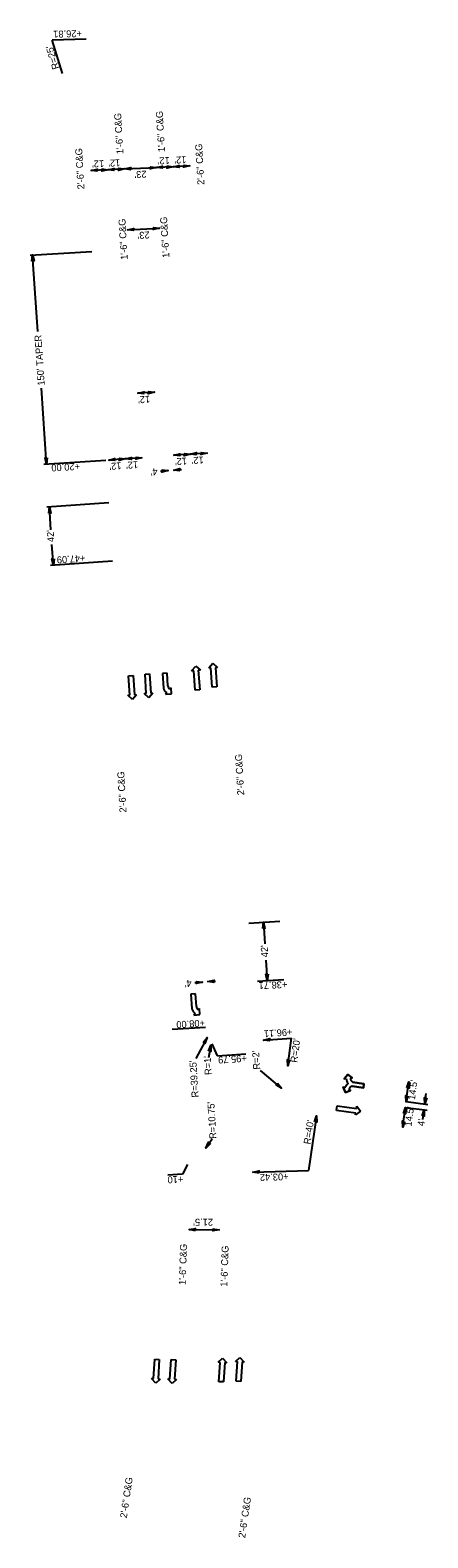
# Model space of a CAD drawing. Extents: x 2320991 to 2332664, y 598057 to 612602.
# Drawn here: x 2328311 to 2328598, y 604198 to 605283 of the extents above; entities that cross this region are included whole.
import ezdxf

# ---------------------------------------------------------------- set-up
doc = ezdxf.new("R2010")
doc.units = 0
for name, color, linetype in [('Prop Dimension', 7, 'Continuous'), ('Prop Dimension Text', 7, 'Continuous'), ('Prop Lane Arrow CELL', 7, 'Continuous'), ('Prop Terminator CELL', 7, 'Continuous')]:
    doc.layers.add(name, color=color, linetype=linetype)

msp = doc.modelspace()

# ---------------------------------------------------------------- linework, layer by layer
at = {"layer": 'Prop Dimension'}
for p, q in [((2328351.8, 605276.5), (2328327.3, 605275.8)), ((2328334.7, 605252), (2328327.3, 605275.8)), ((2328426.3, 605185.4), (2328414.3, 605184.8)), ((2328367.4, 605182.6), (2328355.4, 605182.1)), ((2328379.4, 605183.2), (2328367.4, 605182.6)), ((2328379.4, 605183.2), (2328402.3, 605184.2)), ((2328414.3, 605184.8), (2328402.3, 605184.3)), ((2328381.5, 605139.4), (2328404.5, 605140.6)), ((2328311.4, 605121.3), (2328355.9, 605123.8)), ((2328316.8, 605066.3), (2328313.1, 605121.4)), ((2328323.2, 604970.8), (2328319.5, 605025.6)), ((2328400.9, 605022.6), (2328388.9, 605021.8)), ((2328321.3, 604970.7), (2328366, 604973.7)), ((2328379.9, 604974.6), (2328368, 604973.8)), ((2328391.9, 604975.4), (2328379.9, 604974.6)), ((2328426.8, 604978), (2328414.8, 604977.2)), ((2328438.8, 604978.8), (2328426.8, 604978)), ((2328405.3, 604965.8), (2328410.8, 604966.2)), ((2328414.8, 604966.5), (2328420.3, 604966.9)), ((2328368, 604942.9), (2328323.3, 604939.9)), ((2328326.4, 604923.6), (2328325.3, 604940)), ((2328328.1, 604898.1), (2328327.1, 604913.1)), ((2328370.8, 604901), (2328326.1, 604898)), ((2328479.4, 604641.2), (2328480.5, 604625.7)), ((2328481.2, 604614), (2328482.2, 604599.3)), ((2328429.9, 604597.9), (2328435.4, 604598.2)), ((2328439.4, 604598.5), (2328444.9, 604598.9)), ((2328437.6, 604565.6), (2328413.7, 604564)), ((2328438.8, 604558.2), (2328430.6, 604543.3)), ((2328479.5, 604556.5), (2328499.5, 604557.8)), ((2328496.9, 604538), (2328499.5, 604557.8)), ((2328441.5, 604552.8), (2328439.9, 604543.6)), ((2328446.2, 604545.1), (2328442.4, 604553.7)), ((2328446.2, 604545.1), (2328466.7, 604546.5)), ((2328492.5, 604521.9), (2328477.4, 604534.5)), ((2328582.5, 604514.5), (2328584.1, 604526.4)), ((2328517.6, 604501.9), (2328511.9, 604462.7)), ((2328580.1, 604496.2), (2328581.6, 604508)), ((2328442.4, 604485.1), (2328438, 604478.7)), ((2328421.1, 604459.9), (2328410.6, 604459.3)), ((2328424.7, 604467), (2328421.1, 604459.9)), ((2328471.8, 604461.5), (2328511.9, 604462.7)), ((2328425.9, 604420.1), (2328447.4, 604419.9))]:
    msp.add_line(p, q, dxfattribs=at)
for points in [[(2328469, 604640.5), (2328491.3, 604642)], [(2328475.2, 604598.9), (2328494.1, 604600.1)]]:
    msp.add_lwpolyline(points, dxfattribs=at)
at = {"layer": 'Prop Dimension Text'}
for p, q in [((2328595.6, 604510.5), (2328596.6, 604518.1)), ((2328581.6, 604508), (2328597.3, 604506)), ((2328582.3, 604512.3), (2328597.8, 604510.2)), ((2328594.1, 604499.3), (2328595.1, 604506.3))]:
    msp.add_line(p, q, dxfattribs=at)
at = {"layer": 'Prop Lane Arrow CELL'}
for p, q in [((2328440.1, 604824.2), (2328443, 604827.6)), ((2328443, 604827.6), (2328446.4, 604824.6)), ((2328382.3, 604818.6), (2328385.6, 604818.8)), ((2328383.2, 604804.6), (2328382.3, 604818.6)), ((2328385.6, 604818.8), (2328386.5, 604804.8)), ((2328394.1, 604819.7), (2328397.4, 604820)), ((2328395, 604805.8), (2328394.1, 604819.7)), ((2328397.4, 604820), (2328398.3, 604806)), ((2328410, 604820.4), (2328406.7, 604820.2)), ((2328406.7, 604820.2), (2328407.4, 604809.7)), ((2328410.6, 604811.3), (2328410, 604820.4)), ((2328427.7, 604822.1), (2328430.6, 604825.5)), ((2328429.2, 604822.2), (2328427.7, 604822.1)), ((2328430.2, 604808.3), (2328429.2, 604822.2)), ((2328430.6, 604825.5), (2328434, 604822.6)), ((2328434, 604822.6), (2328432.5, 604822.5)), ((2328432.5, 604822.5), (2328433.5, 604808.5)), ((2328441.6, 604824.3), (2328440.1, 604824.2)), ((2328442.5, 604810.3), (2328441.6, 604824.3)), ((2328446.4, 604824.6), (2328444.9, 604824.5)), ((2328444.9, 604824.5), (2328445.8, 604810.6)), ((2328393.5, 604805.7), (2328395, 604805.8)), ((2328396.9, 604802.7), (2328393.5, 604805.7)), ((2328399.8, 604806.1), (2328396.9, 604802.7)), ((2328398.3, 604806), (2328399.8, 604806.1)), ((2328409.7, 604806.4), (2328408.8, 604805.3)), ((2328408.8, 604805.3), (2328413.1, 604805.5)), ((2328412.9, 604810), (2328411.9, 604808.9)), ((2328413.1, 604805.5), (2328412.9, 604810)), ((2328433.5, 604808.5), (2328430.2, 604808.3)), ((2328445.8, 604810.6), (2328442.5, 604810.3)), ((2328381.7, 604804.5), (2328383.2, 604804.6)), ((2328385.1, 604801.6), (2328381.7, 604804.5)), ((2328388, 604804.9), (2328385.1, 604801.6)), ((2328386.5, 604804.8), (2328388, 604804.9)), ((2328430.5, 604589.7), (2328427.2, 604589.5)), ((2328427.2, 604589.5), (2328427.9, 604578.9)), ((2328431.1, 604580.6), (2328430.5, 604589.7)), ((2328433.4, 604579.3), (2328432.4, 604578.1)), ((2328433.7, 604574.8), (2328433.4, 604579.3)), ((2328430.2, 604575.6), (2328429.3, 604574.5)), ((2328429.3, 604574.5), (2328433.7, 604574.8)), ((2328537.6, 604528.5), (2328540.1, 604531.7)), ((2328539, 604528.8), (2328537.6, 604528.5)), ((2328540.1, 604531.7), (2328543.2, 604529.3)), ((2328540.2, 604525.4), (2328540.1, 604524.9)), ((2328543.2, 604529.3), (2328541.9, 604529.1)), ((2328543.6, 604526.2), (2328551.8, 604525.1)), ((2328551.8, 604525.1), (2328551.4, 604522.1)), ((2328538.4, 604518.8), (2328536.8, 604522.5)), ((2328536.8, 604522.5), (2328538.1, 604522)), ((2328542, 604520.3), (2328538.4, 604518.8)), ((2328540.8, 604520.9), (2328542, 604520.3)), ((2328551.4, 604522.1), (2328543.2, 604523.2)), ((2328532.1, 604505.9), (2328532.5, 604509.2)), ((2328545.9, 604504), (2328532.1, 604505.9)), ((2328532.5, 604509.2), (2328546.4, 604507.3)), ((2328549.3, 604505.3), (2328545.7, 604502.6)), ((2328545.7, 604502.6), (2328545.9, 604504)), ((2328546.4, 604507.3), (2328546.6, 604508.8)), ((2328546.6, 604508.8), (2328549.3, 604505.3)), ((2328400.3, 604312.9), (2328401.1, 604326.9)), ((2328401.1, 604326.9), (2328404.4, 604326.7)), ((2328404.4, 604326.7), (2328403.6, 604312.7)), ((2328412.1, 604312.6), (2328412.9, 604326.6)), ((2328412.9, 604326.6), (2328416.2, 604326.4)), ((2328416.2, 604326.4), (2328415.4, 604312.4)), ((2328446.7, 604324.7), (2328450, 604327.7)), ((2328448.2, 604324.6), (2328446.7, 604324.7)), ((2328447.3, 604310.6), (2328448.2, 604324.6)), ((2328450, 604327.7), (2328453, 604324.3)), ((2328451.5, 604324.4), (2328450.6, 604310.5)), ((2328453, 604324.3), (2328451.5, 604324.4)), ((2328459.2, 604325.2), (2328462.5, 604328.2)), ((2328460.7, 604325.1), (2328459.2, 604325.2)), ((2328459.8, 604311.1), (2328460.7, 604325.1)), ((2328462.5, 604328.2), (2328465.5, 604324.8)), ((2328464, 604324.9), (2328463.1, 604310.9)), ((2328465.5, 604324.8), (2328464, 604324.9)), ((2328401.8, 604309.7), (2328398.8, 604313)), ((2328398.8, 604313), (2328400.3, 604312.9)), ((2328405, 604312.6), (2328401.8, 604309.7)), ((2328403.6, 604312.7), (2328405, 604312.6)), ((2328413.6, 604309.4), (2328410.6, 604312.7)), ((2328410.6, 604312.7), (2328412.1, 604312.6)), ((2328416.9, 604312.3), (2328413.6, 604309.4)), ((2328415.4, 604312.4), (2328416.9, 604312.3)), ((2328450.6, 604310.5), (2328447.3, 604310.6)), ((2328463.1, 604310.9), (2328459.8, 604311.1))]:
    msp.add_line(p, q, dxfattribs=at)
for points in [[(2328541.9, 604529.1), (2328543.2, 604529.3), (2328540.1, 604531.7), (2328537.6, 604528.5), (2328539, 604528.8)], [(2328540.2, 604525.4), (2328540.1, 604524.9)], [(2328542.6, 604527.1), (2328542.6, 604527.1)], [(2328543.2, 604523.2), (2328551.4, 604522.1), (2328551.8, 604525.1), (2328543.6, 604526.2)], [(2328538.1, 604522), (2328536.8, 604522.5), (2328538.4, 604518.8), (2328542, 604520.3), (2328540.8, 604520.9)], [(2328542, 604522.6), (2328542, 604522.6)]]:
    msp.add_lwpolyline(points, dxfattribs=at)
for centre, radius, start, end in [((2328412.5, 604810.8), 5.25, 192.6657, 237.9774), ((2328413.8, 604811.5), 3.27, 183.9897, 233.6478), ((2328433, 604580.1), 5.25, 192.6657, 237.9774), ((2328434.4, 604580.8), 3.27, 183.9897, 233.6478), ((2328544.6, 604519.6), 6.97, 129.874, 159.7268), ((2328544.6, 604519.6), 6.97, 129.874, 159.7268), ((2328545.9, 604529.4), 6.97, 185.3103, 215.0057), ((2328545.9, 604529.4), 6.97, 185.3103, 215.0057), ((2328545.9, 604529.4), 4, 184.0704, 215.0005), ((2328545.9, 604529.4), 4, 184.0704, 215.0005), ((2328544.6, 604528.3), 2.28, 211.5104, 246.2764), ((2328544.6, 604528.3), 2.28, 211.5104, 246.2764), ((2328544.6, 604519.6), 4, 129.874, 161.0867), ((2328544.6, 604519.6), 4, 129.874, 161.0867), ((2328543.6, 604521), 2.28, 100.3662, 133.3641), ((2328543.6, 604521), 2.28, 100.3662, 133.3641)]:
    msp.add_arc(centre, radius, start, end, dxfattribs=at)
at = {"layer": 'Prop Terminator CELL'}
for points in [[(2328406.9, 605183.7), (2328402.3, 605184.3), (2328406.8, 605185.3), (2328406.3, 605184.5)], [(2328409.8, 605185.4), (2328414.3, 605184.8), (2328409.8, 605183.8), (2328410.4, 605184.6)], [(2328418.9, 605184.2), (2328414.3, 605184.8), (2328418.8, 605185.8), (2328418.3, 605185)], [(2328421.8, 605185.9), (2328426.3, 605185.4), (2328421.8, 605184.4), (2328422.4, 605185.2)], [(2328359.9, 605181.5), (2328355.4, 605182.1), (2328359.9, 605183.1), (2328359.3, 605182.3)], [(2328362.9, 605183.2), (2328367.4, 605182.6), (2328362.9, 605181.6), (2328363.4, 605182.5)], [(2328371.9, 605182.1), (2328367.4, 605182.6), (2328371.9, 605183.6), (2328371.3, 605182.8)], [(2328374.8, 605183.8), (2328379.4, 605183.2), (2328374.9, 605182.2), (2328375.4, 605183)], [(2328383.9, 605182.6), (2328379.4, 605183.2), (2328383.9, 605184.2), (2328383.3, 605183.4)], [(2328397.8, 605184.8), (2328402.3, 605184.2), (2328397.9, 605183.2), (2328398.4, 605184.1)], [(2328386.1, 605138.9), (2328381.5, 605139.4), (2328386, 605140.4), (2328385.5, 605139.6)], [(2328400, 605141.2), (2328404.5, 605140.6), (2328400, 605139.6), (2328400.5, 605140.4)], [(2328312.6, 605116.9), (2328313.1, 605121.4), (2328314.2, 605117), (2328313.4, 605117.5)], [(2328393.4, 605021.3), (2328388.9, 605021.8), (2328393.4, 605022.9), (2328392.8, 605022)], [(2328396.3, 605023), (2328400.9, 605022.6), (2328396.4, 605021.5), (2328396.9, 605022.3)], [(2328431.3, 604977.6), (2328426.8, 604978), (2328431.3, 604979.1), (2328430.7, 604978.3)], [(2328434.2, 604979.3), (2328438.8, 604978.8), (2328434.3, 604977.7), (2328434.8, 604978.6)], [(2328323.6, 604975.4), (2328323.2, 604970.8), (2328322.1, 604975.3), (2328322.9, 604974.8)], [(2328372.5, 604973.4), (2328368, 604973.8), (2328372.4, 604974.9), (2328371.9, 604974.1)], [(2328375.4, 604975.1), (2328379.9, 604974.6), (2328375.5, 604973.5), (2328376, 604974.4)], [(2328384.5, 604974.2), (2328379.9, 604974.6), (2328384.4, 604975.7), (2328383.9, 604974.9)], [(2328387.4, 604975.9), (2328391.9, 604975.4), (2328387.4, 604974.3), (2328388, 604975.2)], [(2328419.4, 604976.8), (2328414.8, 604977.2), (2328419.3, 604978.3), (2328418.8, 604977.5)], [(2328422.3, 604978.5), (2328426.8, 604978), (2328422.3, 604976.9), (2328422.9, 604977.8)], [(2328406.3, 604966.7), (2328410.8, 604966.2), (2328406.3, 604965.1), (2328406.9, 604966)], [(2328419.3, 604966), (2328414.8, 604966.5), (2328419.3, 604967.6), (2328418.7, 604966.7)], [(2328324.9, 604935.5), (2328325.3, 604940), (2328326.4, 604935.6), (2328325.6, 604936.1)], [(2328328.6, 604902.6), (2328328.1, 604898.1), (2328327, 604902.6), (2328327.9, 604902)], [(2328478.9, 604636.7), (2328479.4, 604641.2), (2328480.5, 604636.8), (2328479.7, 604637.3)], [(2328443.9, 604598), (2328439.4, 604598.5), (2328443.8, 604599.6), (2328443.3, 604598.8)], [(2328482.7, 604603.9), (2328482.2, 604599.3), (2328481.1, 604603.8), (2328482, 604603.3)], [(2328430.9, 604598.7), (2328435.4, 604598.2), (2328430.9, 604597.1), (2328431.5, 604598)], [(2328436, 604554.7), (2328438.8, 604558.2), (2328437.3, 604553.9), (2328436.9, 604554.8)], [(2328484.1, 604556), (2328479.5, 604556.5), (2328484, 604557.6), (2328483.5, 604556.7)], [(2328439.9, 604548.5), (2328441.5, 604552.8), (2328441.5, 604548.2), (2328440.8, 604548.9)], [(2328498.2, 604542.3), (2328496.9, 604538), (2328496.7, 604542.6), (2328497.4, 604541.9)], [(2328489.5, 604525.4), (2328492.5, 604521.9), (2328488.5, 604524.2), (2328489.5, 604524.4)], [(2328582.7, 604522), (2328584.1, 604526.4), (2328584.3, 604521.8), (2328583.6, 604522.5)], [(2328583.5, 604516.4), (2328582.2, 604512), (2328582, 604516.6), (2328582.7, 604515.9)], [(2328597, 604514.9), (2328595.6, 604510.5), (2328595.4, 604515.1), (2328596.1, 604514.4)], [(2328516.2, 604497.6), (2328517.6, 604501.9), (2328517.8, 604497.3), (2328517.1, 604498)], [(2328580.3, 604503.7), (2328581.6, 604508), (2328581.8, 604503.5), (2328581.1, 604504.1)], [(2328593.7, 604501.9), (2328595.1, 604506.3), (2328595.2, 604501.7), (2328594.5, 604502.4)], [(2328581.1, 604498), (2328579.7, 604493.7), (2328579.5, 604498.3), (2328580.2, 604497.6)], [(2328441.2, 604482), (2328438, 604478.7), (2328439.9, 604482.9), (2328440.3, 604482)], [(2328476.4, 604460.8), (2328471.8, 604461.5), (2328476.3, 604462.4), (2328475.8, 604461.6)], [(2328430.4, 604419.3), (2328425.9, 604420.1), (2328430.4, 604420.8), (2328429.9, 604420.1)], [(2328442.9, 604420.7), (2328447.4, 604419.9), (2328442.9, 604419.2), (2328443.5, 604420)]]:
    msp.add_lwpolyline(points, close=True, dxfattribs=at)

# ---------------------------------------------------------------- texts
at = {"layer": 'Prop Dimension'}
for s, rotation, p in [('+26.81', 181.7116, (2328348.6, 605283.2)), ('+20.00', 183.5952, (2328347.1, 604971.8)), ('+47.09', 183.8226, (2328351, 604905.7)), ('+38.71', 182.1908, (2328496.5, 604598.9)), ('+08.00', 183.8226, (2328437.1, 604571.3)), ('+96.11', 183.8226, (2328500.1, 604564.8)), ('+95.79', 183.8226, (2328467.2, 604545.9)), ('+10', 182.0102, (2328421.6, 604458.8)), ('+03.42', 181.7503, (2328497.4, 604460.7))]:
    msp.add_text(s, height=5, rotation=rotation, dxfattribs=at).set_placement(p)
at = {"layer": 'Prop Dimension Text'}
for s, rotation, p in [("R=25'", 106.8786, (2328332.4, 605255.7)), ('1\'-6" C&G', 93.4385, (2328378.6, 605194)), ('1\'-6" C&G', 93.4385, (2328408.6, 605195.5)), ('2\'-6" C&G', 93.3267, (2328350.5, 605168.7)), ('2\'-6" C&G', 93.3267, (2328436.9, 605171.9)), ("12'", 182.6098, (2328364.5, 605189.6)), ("12'", 182.6098, (2328376.2, 605190.2)), ("12'", 182.6098, (2328411.8, 605191.8)), ("12'", 182.6098, (2328423.8, 605192.4)), ("23'", 182.8519, (2328395.1, 605182)), ('1\'-6" C&G', 93.4385, (2328381.7, 605118)), ('1\'-6" C&G', 93.4385, (2328411.7, 605119.4)), ("23'", 183.2978, (2328397.3, 605138.3)), ("150' TAPER", 93.8226, (2328321.9, 605027.5)), ("12'", 183.8226, (2328397.6, 605020.1)), ("12'", 183.8226, (2328377, 604972.2)), ("12'", 183.8226, (2328389, 604973)), ("12'", 183.8226, (2328424.2, 604975.6)), ("12'", 183.8226, (2328436.2, 604976.4)), ("4'", 183.8226, (2328403, 604967.9)), ("42'", 93.4105, (2328328.8, 604914.9)), ('2\'-6" C&G', 93.3267, (2328465.6, 604732.8)), ('2\'-6" C&G', 93.3267, (2328380.8, 604720.3)), ("42'", 93.4105, (2328482.9, 604616.2)), ("4'", 183.8226, (2328427.5, 604599.8)), ("R=20'", 82.4979, (2328503.7, 604540)), ("R=2'", 93.8226, (2328477.1, 604535.4)), ("R=39.25'", 93.4385, (2328432.7, 604515.3)), ("R=1'", 93.4385, (2328442.2, 604531.5)), ("14.5'", 82.4373, (2328588.5, 604513.2)), ("R=10.75'", 93.4385, (2328445.6, 604485.5)), ("14.5'", 82.4373, (2328586, 604494.1)), ("R=40'", 81.4941, (2328513.2, 604481.2)), ("4'", 82.4373, (2328595.2, 604494.3)), ("21.5'", 179.8336, (2328443.1, 604427.9)), ('1\'-6" C&G', 88.1916, (2328423.4, 604380.2)), ('1\'-6" C&G', 88.1916, (2328453.4, 604378.9)), ('2\'-6" C&G', 81.7191, (2328381, 604212.3)), ('2\'-6" C&G', 81.7191, (2328466.2, 604198))]:
    msp.add_text(s, height=5, rotation=rotation, dxfattribs=at).set_placement(p)

doc.saveas('drawing.dxf')
